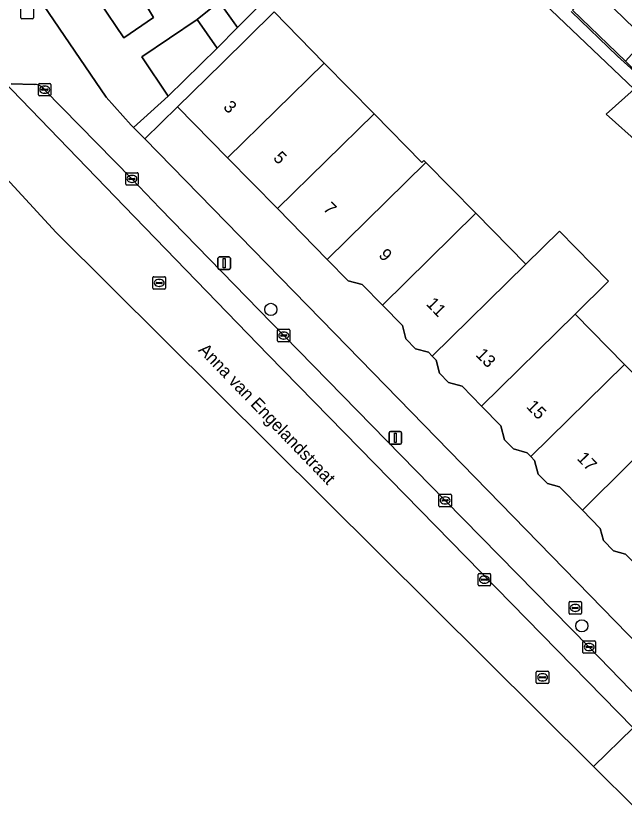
# Model space of a CAD drawing. Extents: x 159960 to 160866, y 382700 to 383354.
# Drawn here: x 160434.5 to 160483.3, y 382767.4 to 382832 of the extents above; entities that cross this region are included whole.
import ezdxf

# ---------------------------------------------------------------- set-up
doc = ezdxf.new("R2010")
doc.units = 0
for name, color, linetype in [('IMGEO_Boom', 7, 'Continuous'), ('IMGEO_Brandkraan', 7, 'Continuous'), ('IMGEO_Erf', 7, 'Continuous'), ('IMGEO_Kolk', 7, 'Continuous'), ('IMGEO_Lichtmast', 7, 'Continuous'), ('IMGEO_Openbare_ruimte_label', 7, 'Continuous'), ('IMGEO_Pand', 7, 'Continuous'), ('IMGEO_Pand_nummerreeks', 7, 'Continuous'), ('IMGEO_Parkeervlak_open', 7, 'Continuous'), ('IMGEO_Rijbaan_lokaal_open', 7, 'Continuous'), ('IMGEO_Rioolput', 7, 'Continuous'), ('IMGEO_Voetpad_open', 7, 'Continuous')]:
    doc.layers.add(name, color=color, linetype=linetype)

msp = doc.modelspace()

# ---------------------------------------------------------------- linework, layer by layer
at = {"layer": 'IMGEO_Boom'}
for centre in [(160454.881, 382808.505), (160479.8, 382783.146)]:
    msp.add_circle(centre, 0.489, dxfattribs=at)
at = {"layer": 'IMGEO_Brandkraan'}
for p, q in [((160434.856, 382831.865), (160434.856, 382832.717)), ((160435.857, 382832.717), (160435.857, 382831.865)), ((160435.783, 382831.791), (160434.931, 382831.791)), ((160478.852, 382785.089), (160479.704, 382785.089)), ((160478.777, 382784.163), (160478.777, 382785.015)), ((160479.036, 382784.583), (160479.036, 382784.595)), ((160479.474, 382784.546), (160479.076, 382784.546)), ((160479.079, 382784.632), (160479.477, 382784.632)), ((160479.265, 382784.869), (160479.29, 382784.869)), ((160479.52, 382784.595), (160479.52, 382784.583)), ((160479.778, 382785.015), (160479.778, 382784.163)), ((160479.704, 382784.089), (160478.852, 382784.089)), ((160479.288, 382784.309), (160479.263, 382784.309))]:
    msp.add_line(p, q, dxfattribs=at)
for points in [[(160434.856, 382831.865), (160434.856, 382832.717)], [(160435.857, 382832.717), (160435.857, 382831.865)], [(160435.783, 382831.791), (160434.931, 382831.791)], [(160478.852, 382785.089), (160479.704, 382785.089)], [(160478.777, 382784.163), (160478.777, 382785.015)], [(160479.778, 382785.015), (160479.778, 382784.163)], [(160479.704, 382784.089), (160478.852, 382784.089)]]:
    msp.add_lwpolyline(points, dxfattribs=at)
for centre, radius, start, end in [((160434.933, 382831.867), 0.0765, 181.55205, 268.44795), ((160434.933, 382831.867), 0.0765, 181.55205, 268.44795), ((160435.781, 382831.867), 0.0765, 271.55205, 358.44795), ((160435.781, 382831.867), 0.0765, 271.55205, 358.44795), ((160478.854, 382785.013), 0.0765, 91.55205, 178.44795), ((160478.854, 382785.013), 0.0765, 91.55205, 178.44795), ((160479.702, 382785.013), 0.0765, 1.55205, 88.44795), ((160479.702, 382785.013), 0.0765, 1.55205, 88.44795), ((160479.076, 382784.592), 0.0403, 85.87752, 175.75265), ((160479.073, 382784.582), 0.0366, 178.93798, 274.71019), ((160479.477, 382784.589), 0.043, 264.86636, 352.45326), ((160479.481, 382784.594), 0.0386, 1.73085, 96.63898), ((160478.854, 382784.165), 0.0765, 181.55205, 268.44795), ((160478.854, 382784.165), 0.0765, 181.55205, 268.44795), ((160479.702, 382784.165), 0.0765, 271.55205, 358.44795), ((160479.702, 382784.165), 0.0765, 271.55205, 358.44795)]:
    msp.add_arc(centre, radius, start, end, dxfattribs=at)
for centre, major_axis, ratio, start_param, end_param in [((160479.264, 382784.589), (-0.387, 0.002), 0.722429, 4.712389, 7.853982), ((160479.289, 382784.589), (-0.39, 0.002), 0.717154, 1.570796, 4.712389)]:
    msp.add_ellipse(centre, major_axis=major_axis, ratio=ratio, start_param=start_param, end_param=end_param, dxfattribs=at)
at = {"layer": 'IMGEO_Erf'}
for points in [[(160484.504, 382821.682), (160481.748, 382824.135), (160484.007, 382826.137), (160471.217, 382838.323)], [(160444.296, 382833.872), (160445.488, 382831.886), (160443.09, 382830.271), (160439.19, 382836.06)], [(160435.396, 382834.737), (160441.686, 382825.501), (160443.696, 382823.273), (160443.886, 382823.079), (160446.657, 382825.579), (160444.534, 382828.73), (160448.971, 382831.72), (160450.74, 382833.147), (160452.198, 382831.078), (160456.566, 382835.472)], [(160480.701, 382834.252), (160484.891, 382830.185), (160485.375, 382830.73), (160489.441, 382826.782), (160493.331, 382823.319), (160495.4, 382821.477), (160493.021, 382818.805), (160496.274, 382815.907), (160498.365, 382818.196), (160501.209, 382815.599), (160499.151, 382813.344), (160503.404, 382809.555), (160512.357, 382819.658), (160508.147, 382823.389), (160504.015, 382827.051), (160500, 382830.609), (160499.883, 382830.712), (160495.769, 382834.359)], [(160455.146, 382832.332), (160459.161, 382828.243), (160463.155, 382824.175), (160466.988, 382820.271), (160467.155, 382820.435), (160467.314, 382820.273), (160471.311, 382816.202), (160475.319, 382812.12), (160478.014, 382814.766), (160481.952, 382810.756), (160479.257, 382808.11), (160483.217, 382804.077), (160487.361, 382799.856)], [(160478.962, 382832.368), (160482.656, 382828.781), (160485.317, 382826.413), (160483.291, 382828.38), (160479.067, 382832.481)], [(160483.312, 382788.903), (160482.344, 382789.172), (160481.533, 382789.998), (160481.284, 382790.96), (160479.858, 382792.413), (160478.026, 382794.279), (160477.045, 382794.551), (160476.301, 382795.309), (160476.017, 382796.41), (160475.717, 382796.715), (160475.419, 382797.018), (160474.335, 382797.32), (160473.616, 382798.052), (160473.325, 382799.18), (160471.772, 382800.762), (160470.22, 382802.343), (160469.132, 382802.645), (160468.396, 382803.394), (160468.124, 382804.448), (160467.82, 382804.758), (160467.517, 382805.066), (160466.473, 382805.356), (160465.706, 382806.138), (160465.43, 382807.204), (160463.817, 382808.847), (160462.202, 382810.492), (160461.081, 382810.804), (160459.407, 382812.509), (160455.414, 382816.576), (160451.42, 382820.643), (160447.406, 382824.732), (160444.778, 382822.165), (160459.989, 382806.589), (160488.628, 382777.217)]]:
    msp.add_lwpolyline(points, dxfattribs=at)
at = {"layer": 'IMGEO_Kolk'}
for p, q in [((160436.257, 382825.682), (160436.257, 382826.534)), ((160436.332, 382826.608), (160437.184, 382826.608)), ((160436.745, 382826.388), (160436.77, 382826.388)), ((160437.258, 382826.534), (160437.258, 382825.682)), ((160436.516, 382826.102), (160436.516, 382826.114)), ((160436.954, 382826.065), (160436.556, 382826.065)), ((160436.559, 382826.151), (160436.957, 382826.151)), ((160436.768, 382825.828), (160436.743, 382825.828)), ((160437, 382826.114), (160437, 382826.102)), ((160437.184, 382825.608), (160436.332, 382825.608)), ((160443.253, 382818.53), (160443.253, 382819.382)), ((160443.328, 382819.456), (160444.18, 382819.456)), ((160443.741, 382819.236), (160443.766, 382819.236)), ((160444.254, 382819.382), (160444.254, 382818.53)), ((160443.512, 382818.95), (160443.512, 382818.962)), ((160443.95, 382818.913), (160443.552, 382818.913)), ((160443.555, 382818.999), (160443.953, 382818.999)), ((160443.764, 382818.676), (160443.739, 382818.676)), ((160443.996, 382818.962), (160443.996, 382818.95)), ((160444.18, 382818.456), (160443.328, 382818.456)), ((160455.41, 382805.985), (160455.41, 382806.837)), ((160455.485, 382806.911), (160456.337, 382806.911)), ((160455.669, 382806.405), (160455.669, 382806.417)), ((160456.107, 382806.368), (160455.709, 382806.368)), ((160455.712, 382806.454), (160456.11, 382806.454)), ((160455.898, 382806.691), (160455.923, 382806.691)), ((160456.153, 382806.417), (160456.153, 382806.405)), ((160456.411, 382806.837), (160456.411, 382805.985)), ((160456.337, 382805.911), (160455.485, 382805.911)), ((160455.921, 382806.131), (160455.896, 382806.131)), ((160468.348, 382792.772), (160468.348, 382793.624)), ((160468.423, 382793.698), (160469.275, 382793.698)), ((160468.836, 382793.478), (160468.861, 382793.478)), ((160469.349, 382793.624), (160469.349, 382792.772)), ((160468.607, 382793.192), (160468.607, 382793.204)), ((160469.045, 382793.155), (160468.647, 382793.155)), ((160468.65, 382793.241), (160469.048, 382793.241)), ((160468.859, 382792.918), (160468.834, 382792.918)), ((160469.091, 382793.204), (160469.091, 382793.192)), ((160469.275, 382792.698), (160468.423, 382792.698)), ((160479.896, 382781.026), (160479.896, 382781.878)), ((160479.971, 382781.952), (160480.823, 382781.952)), ((160480.897, 382781.878), (160480.897, 382781.026)), ((160480.155, 382781.446), (160480.155, 382781.458)), ((160480.593, 382781.409), (160480.195, 382781.409)), ((160480.198, 382781.495), (160480.596, 382781.495)), ((160480.407, 382781.172), (160480.382, 382781.172)), ((160480.384, 382781.732), (160480.409, 382781.732)), ((160480.639, 382781.458), (160480.639, 382781.446)), ((160480.823, 382780.952), (160479.971, 382780.952))]:
    msp.add_line(p, q, dxfattribs=at)
for points in [[(160436.257, 382825.682), (160436.257, 382826.534)], [(160436.332, 382826.608), (160437.184, 382826.608)], [(160437.258, 382826.534), (160437.258, 382825.682)], [(160437.184, 382825.608), (160436.332, 382825.608)], [(160443.253, 382818.53), (160443.253, 382819.382)], [(160443.328, 382819.456), (160444.18, 382819.456)], [(160444.254, 382819.382), (160444.254, 382818.53)], [(160444.18, 382818.456), (160443.328, 382818.456)], [(160455.41, 382805.985), (160455.41, 382806.837)], [(160455.485, 382806.911), (160456.337, 382806.911)], [(160456.411, 382806.837), (160456.411, 382805.985)], [(160456.337, 382805.911), (160455.485, 382805.911)], [(160468.348, 382792.772), (160468.348, 382793.624)], [(160468.423, 382793.698), (160469.275, 382793.698)], [(160469.349, 382793.624), (160469.349, 382792.772)], [(160469.275, 382792.698), (160468.423, 382792.698)], [(160479.896, 382781.026), (160479.896, 382781.878)], [(160479.971, 382781.952), (160480.823, 382781.952)], [(160480.897, 382781.878), (160480.897, 382781.026)], [(160480.823, 382780.952), (160479.971, 382780.952)]]:
    msp.add_lwpolyline(points, dxfattribs=at)
for centre, radius, start, end in [((160436.334, 382826.532), 0.0765, 91.55205, 178.44795), ((160436.334, 382826.532), 0.0765, 91.55205, 178.44795), ((160437.182, 382826.532), 0.0765, 1.55205, 88.44795), ((160437.182, 382826.532), 0.0765, 1.55205, 88.44795), ((160436.556, 382826.111), 0.0403, 85.87752, 175.75265), ((160436.553, 382826.101), 0.0366, 178.93798, 274.71019), ((160436.957, 382826.108), 0.043, 264.86636, 352.45326), ((160436.961, 382826.113), 0.0386, 1.73085, 96.63898), ((160436.334, 382825.684), 0.0765, 181.55205, 268.44795), ((160436.334, 382825.684), 0.0765, 181.55205, 268.44795), ((160437.182, 382825.684), 0.0765, 271.55205, 358.44795), ((160437.182, 382825.684), 0.0765, 271.55205, 358.44795), ((160443.33, 382819.38), 0.0765, 91.55205, 178.44795), ((160443.33, 382819.38), 0.0765, 91.55205, 178.44795), ((160444.178, 382819.38), 0.0765, 1.55205, 88.44795), ((160444.178, 382819.38), 0.0765, 1.55205, 88.44795), ((160443.552, 382818.959), 0.0403, 85.87752, 175.75265), ((160443.549, 382818.949), 0.0366, 178.93798, 274.71019), ((160443.953, 382818.956), 0.043, 264.86636, 352.45326), ((160443.957, 382818.961), 0.0386, 1.73085, 96.63898), ((160443.33, 382818.532), 0.0765, 181.55205, 268.44795), ((160443.33, 382818.532), 0.0765, 181.55205, 268.44795), ((160444.178, 382818.532), 0.0765, 271.55205, 358.44795), ((160444.178, 382818.532), 0.0765, 271.55205, 358.44795), ((160455.487, 382806.835), 0.0765, 91.55205, 178.44795), ((160455.487, 382806.835), 0.0765, 91.55205, 178.44795), ((160455.709, 382806.414), 0.0403, 85.87752, 175.75265), ((160455.706, 382806.404), 0.0366, 178.93798, 274.71019), ((160456.11, 382806.411), 0.043, 264.86636, 352.45326), ((160456.114, 382806.416), 0.0386, 1.73085, 96.63898), ((160456.335, 382806.835), 0.0765, 1.55205, 88.44795), ((160456.335, 382806.835), 0.0765, 1.55205, 88.44795), ((160455.487, 382805.987), 0.0765, 181.55205, 268.44795), ((160455.487, 382805.987), 0.0765, 181.55205, 268.44795), ((160456.335, 382805.987), 0.0765, 271.55205, 358.44795), ((160456.335, 382805.987), 0.0765, 271.55205, 358.44795), ((160468.425, 382793.622), 0.0765, 91.55205, 178.44795), ((160468.425, 382793.622), 0.0765, 91.55205, 178.44795), ((160469.273, 382793.622), 0.0765, 1.55205, 88.44795), ((160469.273, 382793.622), 0.0765, 1.55205, 88.44795), ((160468.425, 382792.774), 0.0765, 181.55205, 268.44795), ((160468.425, 382792.774), 0.0765, 181.55205, 268.44795), ((160468.647, 382793.201), 0.0403, 85.87752, 175.75265), ((160468.644, 382793.191), 0.0366, 178.93798, 274.71019), ((160469.048, 382793.198), 0.043, 264.86636, 352.45326), ((160469.052, 382793.203), 0.0386, 1.73085, 96.63898), ((160469.273, 382792.774), 0.0765, 271.55205, 358.44795), ((160469.273, 382792.774), 0.0765, 271.55205, 358.44795), ((160479.973, 382781.876), 0.0765, 91.55205, 178.44795), ((160479.973, 382781.876), 0.0765, 91.55205, 178.44795), ((160480.821, 382781.876), 0.0765, 1.55205, 88.44795), ((160480.821, 382781.876), 0.0765, 1.55205, 88.44795), ((160480.195, 382781.455), 0.0403, 85.87752, 175.75265), ((160480.192, 382781.445), 0.0366, 178.93798, 274.71019), ((160480.596, 382781.452), 0.043, 264.86636, 352.45326), ((160480.6, 382781.457), 0.0386, 1.73085, 96.63898), ((160479.973, 382781.028), 0.0765, 181.55205, 268.44795), ((160479.973, 382781.028), 0.0765, 181.55205, 268.44795), ((160480.821, 382781.028), 0.0765, 271.55205, 358.44795), ((160480.821, 382781.028), 0.0765, 271.55205, 358.44795)]:
    msp.add_arc(centre, radius, start, end, dxfattribs=at)
for centre, major_axis, ratio, start_param, end_param in [((160436.744, 382826.108), (-0.387, 0.002), 0.722429, 4.712389, 7.853982), ((160436.769, 382826.108), (-0.39, 0.002), 0.717154, 1.570796, 4.712389), ((160443.74, 382818.956), (-0.387, 0.002), 0.722429, 4.712389, 7.853982), ((160443.765, 382818.956), (-0.39, 0.002), 0.717154, 1.570796, 4.712389), ((160455.897, 382806.411), (-0.387, 0.002), 0.722429, 4.712389, 7.853982), ((160455.922, 382806.411), (-0.39, 0.002), 0.717154, 1.570796, 4.712389), ((160468.835, 382793.198), (-0.387, 0.002), 0.722429, 4.712389, 7.853982), ((160468.86, 382793.198), (-0.39, 0.002), 0.717154, 1.570796, 4.712389), ((160480.383, 382781.452), (-0.387, 0.002), 0.722429, 4.712389, 7.853982), ((160480.408, 382781.452), (-0.39, 0.002), 0.717154, 1.570796, 4.712389)]:
    msp.add_ellipse(centre, major_axis=major_axis, ratio=ratio, start_param=start_param, end_param=end_param, dxfattribs=at)
at = {"layer": 'IMGEO_Lichtmast'}
for p, q in [((160450.646, 382811.804), (160450.646, 382812.604)), ((160450.646, 382812.604), (160450.646, 382811.804)), ((160450.746, 382812.704), (160451.536, 382812.704)), ((160451.536, 382812.704), (160450.746, 382812.704)), ((160451.636, 382812.604), (160451.636, 382811.804)), ((160451.636, 382811.804), (160451.636, 382812.604)), ((160451.536, 382811.704), (160450.746, 382811.704)), ((160450.746, 382811.704), (160451.536, 382811.704)), ((160464.362, 382797.81), (160464.362, 382798.61)), ((160464.362, 382798.61), (160464.362, 382797.81)), ((160464.462, 382798.71), (160465.252, 382798.71)), ((160465.252, 382798.71), (160464.462, 382798.71)), ((160465.352, 382798.61), (160465.352, 382797.81)), ((160465.352, 382797.81), (160465.352, 382798.61)), ((160465.252, 382797.71), (160464.462, 382797.71)), ((160464.462, 382797.71), (160465.252, 382797.71))]:
    msp.add_line(p, q, dxfattribs=at)
for points in [[(160451.066, 382812.579), (160451.216, 382812.579), (160451.216, 382811.829), (160451.066, 382811.829), (160451.066, 382812.579)], [(160464.782, 382798.585), (160464.932, 382798.585), (160464.932, 382797.835), (160464.782, 382797.835), (160464.782, 382798.585)]]:
    msp.add_lwpolyline(points, dxfattribs=at)
for centre, start, end in [((160450.746, 382812.604), 90, 180), ((160450.746, 382812.604), 90, 180), ((160451.536, 382812.604), 0, 90), ((160451.536, 382812.604), 360, 90), ((160450.746, 382811.804), 180, 270), ((160450.746, 382811.804), 180, 270), ((160451.536, 382811.804), 270, 0), ((160451.536, 382811.804), 270, 0), ((160464.462, 382798.61), 90, 180), ((160464.462, 382798.61), 90, 180), ((160465.252, 382798.61), 0, 90), ((160465.252, 382798.61), 360, 90), ((160464.462, 382797.81), 180, 270), ((160464.462, 382797.81), 180, 270), ((160465.252, 382797.81), 270, 0), ((160465.252, 382797.81), 270, 0)]:
    msp.add_arc(centre, 0.1, start, end, dxfattribs=at)
at = {"layer": 'IMGEO_Pand'}
for points in [[(160439.543, 382846.025), (160435.496, 382843.299), (160435.959, 382842.613), (160435.176, 382842.086), (160437.817, 382838.166), (160436.984, 382837.605), (160438.388, 382835.52), (160439.19, 382836.06), (160443.09, 382830.271), (160445.488, 382831.886), (160444.296, 382833.872), (160446.669, 382835.476)], [(160480.701, 382834.252), (160479.067, 382832.481), (160483.291, 382828.38), (160484.306, 382829.525), (160484.891, 382830.185)], [(160450.74, 382833.147), (160448.971, 382831.72), (160450.582, 382829.433), (160452.198, 382831.078)], [(160451.42, 382820.643), (160459.161, 382828.243), (160455.146, 382832.332), (160450.974, 382828.235), (160447.406, 382824.732)], [(160446.657, 382825.579), (160450.582, 382829.433), (160448.971, 382831.72), (160444.534, 382828.73)], [(160455.414, 382816.576), (160463.155, 382824.175), (160459.161, 382828.243), (160451.42, 382820.643)], [(160484.007, 382826.137), (160481.748, 382824.135), (160484.504, 382821.682), (160486.543, 382823.489), (160486.763, 382823.684)], [(160455.414, 382816.576), (160459.407, 382812.509), (160467.314, 382820.273), (160467.155, 382820.435), (160466.988, 382820.271), (160463.155, 382824.175)], [(160471.311, 382816.202), (160467.314, 382820.273), (160459.407, 382812.509), (160461.081, 382810.804), (160462.202, 382810.492), (160463.817, 382808.847)], [(160467.82, 382804.758), (160475.319, 382812.12), (160471.311, 382816.202), (160463.817, 382808.847), (160465.43, 382807.204), (160465.706, 382806.138), (160466.473, 382805.356), (160467.517, 382805.066)], [(160471.772, 382800.762), (160479.257, 382808.11), (160481.952, 382810.756), (160478.014, 382814.766), (160475.319, 382812.12), (160467.82, 382804.758), (160468.124, 382804.448), (160468.396, 382803.394), (160469.132, 382802.645), (160470.22, 382802.343)], [(160471.772, 382800.762), (160473.325, 382799.18), (160473.616, 382798.052), (160474.335, 382797.32), (160475.419, 382797.018), (160475.717, 382796.715), (160483.217, 382804.077), (160479.257, 382808.11)], [(160479.858, 382792.413), (160487.361, 382799.856), (160483.217, 382804.077), (160475.717, 382796.715), (160476.017, 382796.41), (160476.301, 382795.309), (160477.045, 382794.551), (160478.026, 382794.279)], [(160491.414, 382795.728), (160494.212, 382798.466), (160490.119, 382802.592), (160487.361, 382799.856), (160479.858, 382792.413), (160481.284, 382790.96), (160481.533, 382789.998), (160482.344, 382789.172), (160483.312, 382788.903), (160483.865, 382788.339)]]:
    msp.add_lwpolyline(points, close=True, dxfattribs=at)
at = {"layer": 'IMGEO_Parkeervlak_open'}
for points in [[(160433.379, 382826.865), (160443.162, 382816.737), (160454.676, 382804.87), (160483.92, 382774.967), (160485.33, 382776.335), (160480.396, 382781.451), (160468.848, 382793.197), (160455.91, 382806.411), (160445.989, 382816.607), (160443.753, 382818.954), (160436.757, 382826.107), (160436.605, 382826.25)], [(160435.926, 382826.53), (160434.075, 382826.587)]]:
    msp.add_lwpolyline(points, dxfattribs=at)
msp.add_arc((160435.956, 382825.639), 0.892, 43.27483, 91.90549, dxfattribs=at)
at = {"layer": 'IMGEO_Rijbaan_lokaal_open'}
for points in [[(160480.738, 382771.882), (160483.92, 382774.967), (160454.676, 382804.87), (160443.162, 382816.737), (160433.379, 382826.865), (160427.731, 382832.608), (160426.207, 382834.302), (160424.636, 382836.452), (160414.071, 382849.137), (160413.926, 382848.999), (160409.257, 382844.54), (160409.257, 382844.54), (160423.582, 382829.971), (160437.672, 382814.656)], [(160484.134, 382768.509), (160487.248, 382771.543), (160483.92, 382774.967), (160480.738, 382771.882)]]:
    msp.add_lwpolyline(points, close=True, dxfattribs=at)
at = {"layer": 'IMGEO_Rioolput'}
for p, q in [((160445.436, 382810.199), (160445.436, 382811.051)), ((160445.511, 382811.125), (160446.363, 382811.125)), ((160445.924, 382810.905), (160445.949, 382810.905)), ((160446.437, 382811.051), (160446.437, 382810.199)), ((160445.695, 382810.619), (160445.695, 382810.631)), ((160446.133, 382810.582), (160445.735, 382810.582)), ((160445.738, 382810.668), (160446.136, 382810.668)), ((160445.947, 382810.345), (160445.922, 382810.345)), ((160446.179, 382810.631), (160446.179, 382810.619)), ((160446.363, 382810.125), (160445.511, 382810.125)), ((160471.493, 382786.424), (160471.493, 382787.276)), ((160471.568, 382787.35), (160472.42, 382787.35)), ((160471.981, 382787.13), (160472.006, 382787.13)), ((160472.494, 382787.276), (160472.494, 382786.424)), ((160472.42, 382786.35), (160471.568, 382786.35)), ((160471.752, 382786.844), (160471.752, 382786.856)), ((160472.19, 382786.807), (160471.792, 382786.807)), ((160471.795, 382786.893), (160472.193, 382786.893)), ((160472.004, 382786.57), (160471.979, 382786.57)), ((160472.236, 382786.856), (160472.236, 382786.844)), ((160476.152, 382778.598), (160476.152, 382779.45)), ((160476.227, 382779.524), (160477.079, 382779.524)), ((160476.64, 382779.304), (160476.665, 382779.304)), ((160477.153, 382779.45), (160477.153, 382778.598)), ((160476.411, 382779.018), (160476.411, 382779.03)), ((160476.849, 382778.981), (160476.451, 382778.981)), ((160476.454, 382779.067), (160476.852, 382779.067)), ((160476.663, 382778.744), (160476.638, 382778.744)), ((160476.895, 382779.03), (160476.895, 382779.018)), ((160477.079, 382778.524), (160476.227, 382778.524))]:
    msp.add_line(p, q, dxfattribs=at)
for points in [[(160445.436, 382810.199), (160445.436, 382811.051)], [(160445.511, 382811.125), (160446.363, 382811.125)], [(160446.437, 382811.051), (160446.437, 382810.199)], [(160446.363, 382810.125), (160445.511, 382810.125)], [(160471.493, 382786.424), (160471.493, 382787.276)], [(160471.568, 382787.35), (160472.42, 382787.35)], [(160472.494, 382787.276), (160472.494, 382786.424)], [(160472.42, 382786.35), (160471.568, 382786.35)], [(160476.152, 382778.598), (160476.152, 382779.45)], [(160476.227, 382779.524), (160477.079, 382779.524)], [(160477.153, 382779.45), (160477.153, 382778.598)], [(160477.079, 382778.524), (160476.227, 382778.524)]]:
    msp.add_lwpolyline(points, dxfattribs=at)
for centre, radius, start, end in [((160445.513, 382811.049), 0.0765, 91.55205, 178.44795), ((160445.513, 382811.049), 0.0765, 91.55205, 178.44795), ((160446.361, 382811.049), 0.0765, 1.55205, 88.44795), ((160446.361, 382811.049), 0.0765, 1.55205, 88.44795), ((160445.513, 382810.201), 0.0765, 181.55205, 268.44795), ((160445.513, 382810.201), 0.0765, 181.55205, 268.44795), ((160445.735, 382810.628), 0.0403, 85.87752, 175.75265), ((160445.732, 382810.618), 0.0366, 178.93798, 274.71019), ((160446.136, 382810.625), 0.043, 264.86636, 352.45326), ((160446.14, 382810.63), 0.0386, 1.73085, 96.63898), ((160446.361, 382810.201), 0.0765, 271.55205, 358.44795), ((160446.361, 382810.201), 0.0765, 271.55205, 358.44795), ((160471.57, 382787.274), 0.0765, 91.55205, 178.44795), ((160471.57, 382787.274), 0.0765, 91.55205, 178.44795), ((160472.418, 382787.274), 0.0765, 1.55205, 88.44795), ((160472.418, 382787.274), 0.0765, 1.55205, 88.44795), ((160471.57, 382786.426), 0.0765, 181.55205, 268.44795), ((160471.57, 382786.426), 0.0765, 181.55205, 268.44795), ((160471.792, 382786.853), 0.0403, 85.87752, 175.75265), ((160471.789, 382786.843), 0.0366, 178.93798, 274.71019), ((160472.193, 382786.85), 0.043, 264.86636, 352.45326), ((160472.197, 382786.855), 0.0386, 1.73085, 96.63898), ((160472.418, 382786.426), 0.0765, 271.55205, 358.44795), ((160472.418, 382786.426), 0.0765, 271.55205, 358.44795), ((160476.229, 382779.448), 0.0765, 91.55205, 178.44795), ((160476.229, 382779.448), 0.0765, 91.55205, 178.44795), ((160477.077, 382779.448), 0.0765, 1.55205, 88.44795), ((160477.077, 382779.448), 0.0765, 1.55205, 88.44795), ((160476.229, 382778.6), 0.0765, 181.55205, 268.44795), ((160476.229, 382778.6), 0.0765, 181.55205, 268.44795), ((160476.451, 382779.027), 0.0403, 85.87752, 175.75265), ((160476.448, 382779.017), 0.0366, 178.93798, 274.71019), ((160476.852, 382779.024), 0.043, 264.86636, 352.45326), ((160476.856, 382779.029), 0.0386, 1.73085, 96.63898), ((160477.077, 382778.6), 0.0765, 271.55205, 358.44795), ((160477.077, 382778.6), 0.0765, 271.55205, 358.44795)]:
    msp.add_arc(centre, radius, start, end, dxfattribs=at)
for centre, major_axis, ratio, start_param, end_param in [((160445.923, 382810.625), (-0.387, 0.002), 0.722429, 4.712389, 7.853982), ((160445.948, 382810.625), (-0.39, 0.002), 0.717154, 1.570796, 4.712389), ((160471.98, 382786.85), (-0.387, 0.002), 0.722429, 4.712389, 7.853982), ((160472.005, 382786.85), (-0.39, 0.002), 0.717154, 1.570796, 4.712389), ((160476.639, 382779.024), (-0.387, 0.002), 0.722429, 4.712389, 7.853982), ((160476.664, 382779.024), (-0.39, 0.002), 0.717154, 1.570796, 4.712389)]:
    msp.add_ellipse(centre, major_axis=major_axis, ratio=ratio, start_param=start_param, end_param=end_param, dxfattribs=at)
at = {"layer": 'IMGEO_Voetpad_open'}
for points in [[(160459.989, 382806.589), (160444.778, 382822.165), (160443.886, 382823.079), (160443.696, 382823.273), (160441.686, 382825.501), (160435.396, 382834.737), (160431.95, 382839.821), (160431.867, 382839.958)], [(160471.217, 382838.323), (160484.007, 382826.137)], [(160456.566, 382835.472), (160452.198, 382831.078), (160450.582, 382829.433), (160446.657, 382825.579), (160443.886, 382823.079), (160444.778, 382822.165), (160447.406, 382824.732), (160450.974, 382828.235), (160455.146, 382832.332)], [(160485.317, 382826.413), (160482.656, 382828.781), (160478.962, 382832.368)], [(160434.075, 382826.587), (160435.926, 382826.53)], [(160436.605, 382826.25), (160436.757, 382826.107), (160443.753, 382818.954), (160445.989, 382816.607), (160455.91, 382806.411), (160468.848, 382793.197), (160480.396, 382781.451), (160485.33, 382776.335), (160488.688, 382772.946), (160495.991, 382765.418), (160500, 382761.296), (160508.925, 382752.119), (160511.001, 382750), (160519.884, 382740.931), (160522.524, 382738.183), (160522.678, 382738.045)], [(160523.01, 382732.609), (160527.056, 382728.093), (160527.826, 382728.864), (160531.076, 382725.317), (160535.292, 382729.461), (160532.79, 382731.991), (160516.438, 382748.678), (160515.15, 382750), (160500, 382765.547), (160489.284, 382776.543), (160488.632, 382777.213), (160488.628, 382777.217), (160459.989, 382806.589)]]:
    msp.add_lwpolyline(points, dxfattribs=at)
msp.add_arc((160435.956, 382825.639), 0.892, 43.27483, 91.90549, dxfattribs=at)

# ---------------------------------------------------------------- texts
at = {"layer": 'IMGEO_Openbare_ruimte_label'}
msp.add_text('Anna van Engelandstraat', height=1, rotation=313.94659, dxfattribs=at).set_placement((160449.01, 382805.195))
at = {"layer": 'IMGEO_Pand_nummerreeks'}
for s, rotation, p in [('3', 314.47486, (160451.011, 382824.657)), ('5', 314.47486, (160455.012, 382820.582)), ('7', 314.47486, (160459.012, 382816.508)), ('9', 314.30309, (160463.46, 382812.796)), ('11', 314.30309, (160467.271, 382808.891)), ('13', 314.30309, (160471.245, 382804.82)), ('15', 314.30309, (160475.298, 382800.667)), ('17', 314.30309, (160479.351, 382796.514))]:
    msp.add_text(s, height=1, rotation=rotation, dxfattribs=at).set_placement(p)

doc.saveas('drawing.dxf')
